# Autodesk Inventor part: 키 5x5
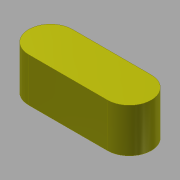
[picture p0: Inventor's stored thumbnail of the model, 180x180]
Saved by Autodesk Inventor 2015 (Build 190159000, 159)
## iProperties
Created: 2014-10
Part Number: 키 5x5
Document SubType Name: Modeling
Designer: KYOUNG IL JANG
Density: 7.86 g/cm^3
Mass: 2.54015 g
Surface Area: 2.9781 cm^2
Volume: 0.323175 cm^3
Material: 강철, 연강
Appearance: 노란색
Author: SeoGD™ [www.esajin.kr]
Revision Number: 1
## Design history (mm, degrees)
sketch "스케치1"
  geometry: L1 (-4.5, -2.5)-(4.5, -2.5); L2 (4.5, 2.5)-(-4.5, 2.5); A1 r 2.5 centre (4.5, 0) between (4.5, -2.5) and (4.5, 2.5); A2 r 2.5 centre (-4.5, 0) between (-4.5, 2.5) and (-4.5, -2.5); 2 further points
  constraints: 4 end point, 4 point on circle, 4 tangent, 2 centre point, 1 horizontal, 1 horizontal alignment, 1 midpoint, 1 parallel, 1 vertical alignment
  dimensions: "d0" = 5 distance between parallel lines of L1 L2; "d1" = 14 dimension on A1 A2
extrude "돌출1" new body sketch "스케치1" stored distance "d2" = 5; taper "d3" = 0 deg
node "솔리드1"
